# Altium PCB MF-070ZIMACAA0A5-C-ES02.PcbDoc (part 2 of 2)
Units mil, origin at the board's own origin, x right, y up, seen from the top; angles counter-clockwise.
Board outline 4023.75 x 4574.93 mil, 4 copper layers (TopLayer, LAYER2:GND, LAYER3:PW, BottomLayer); 140 components, 66 nets, 413 pads, 523 vias.
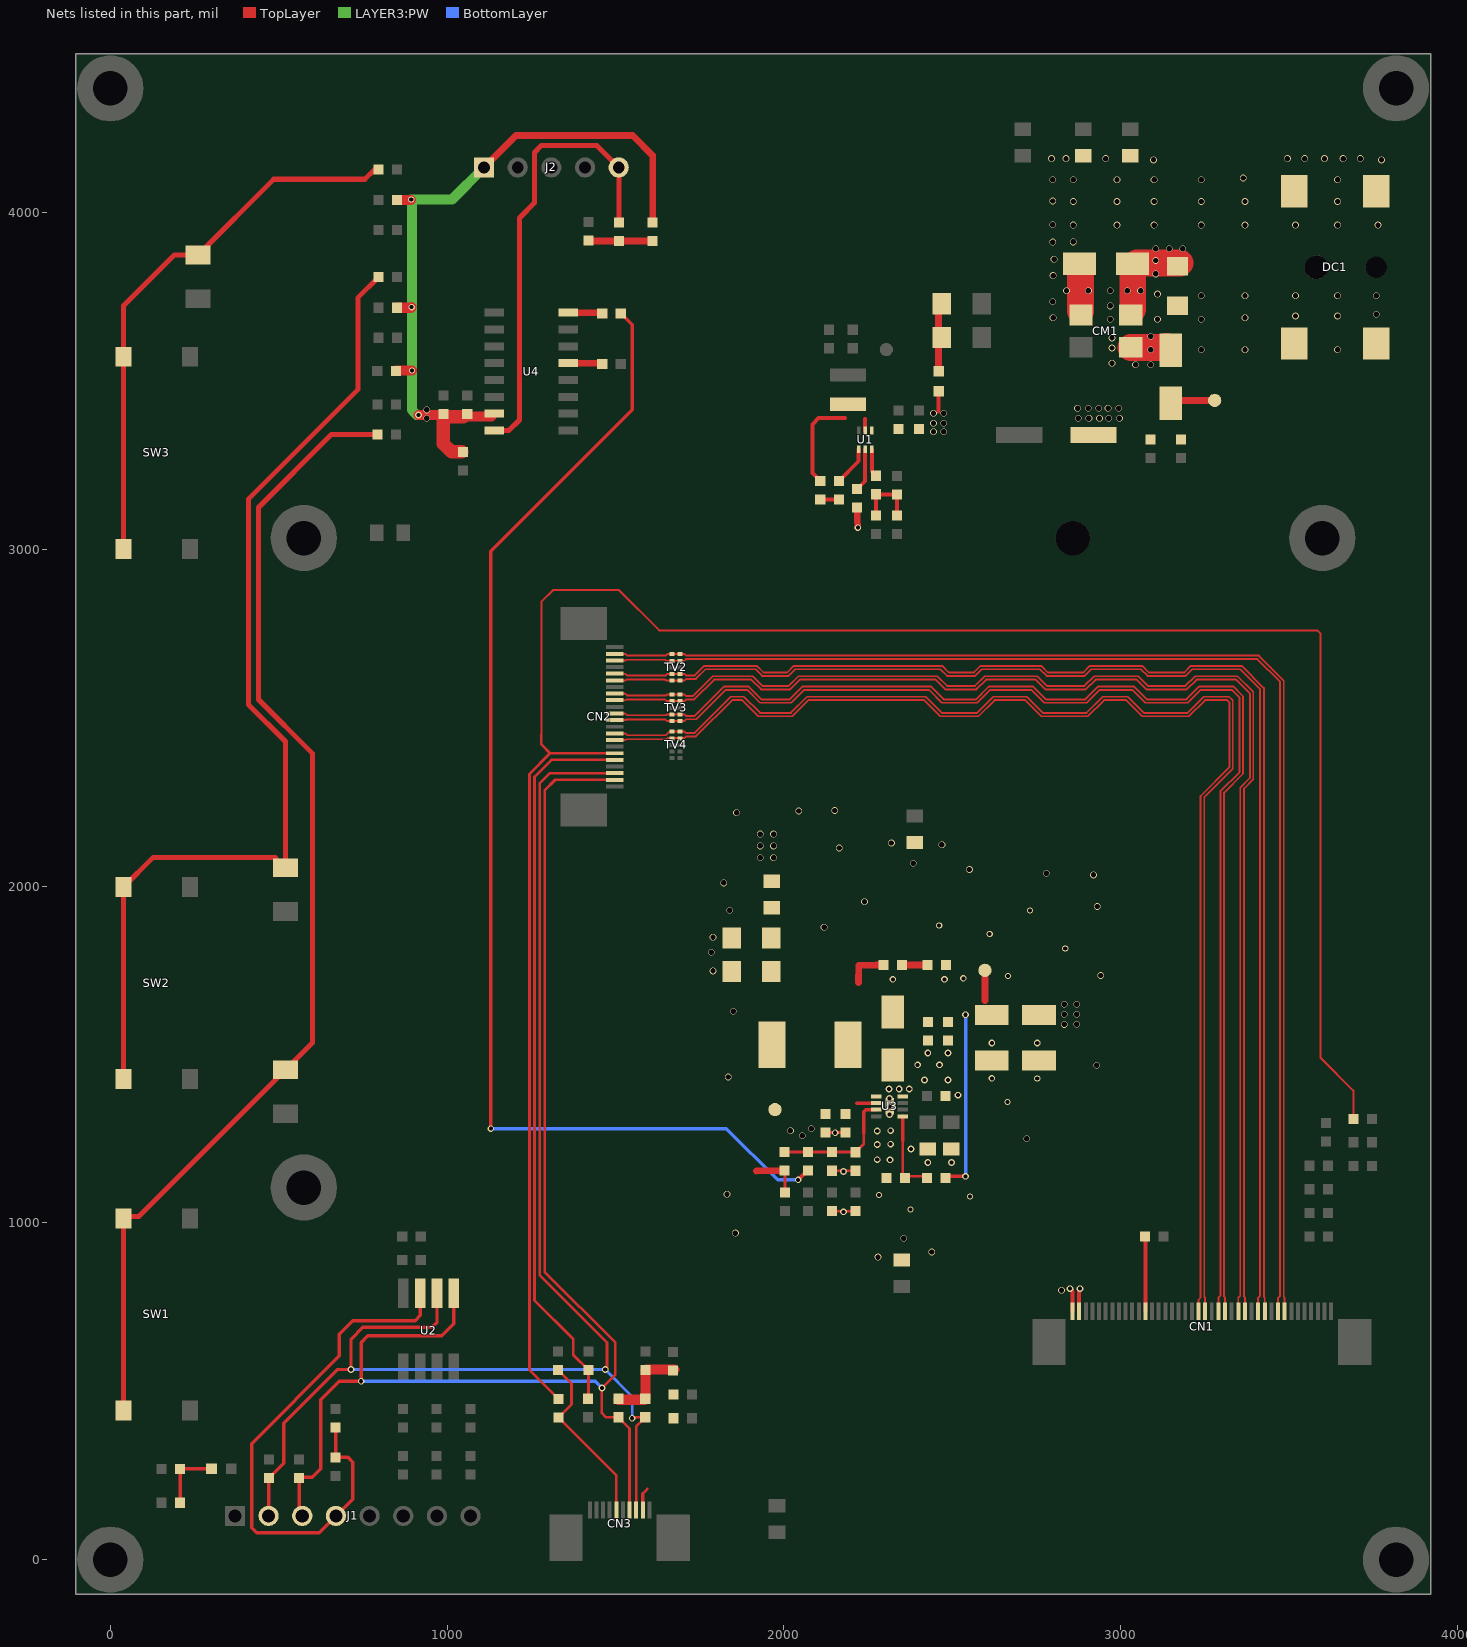
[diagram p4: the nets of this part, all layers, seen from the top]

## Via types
v1: diameter 20, hole 16, TopLayer to BottomLayer, 413 vias
v2: diameter 20, hole 12, TopLayer to BottomLayer, 77 vias
v3: diameter 18, hole 12, TopLayer to BottomLayer, 33 vias

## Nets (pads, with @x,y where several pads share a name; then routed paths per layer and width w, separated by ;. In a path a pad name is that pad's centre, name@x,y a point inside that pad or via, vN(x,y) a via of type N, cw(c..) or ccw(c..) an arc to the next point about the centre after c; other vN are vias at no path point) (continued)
LEDGND: B1.2 B2.2 C17.1 C18.1 C19.1 C20.1 C21.2 C22.1 C23.1 C24.2 C25.2 C35.1 CP5.2 CP6.2 R22.2 R25.2 R27.1 R29.1 R30.1 U3.4 U3.9 | length 202
  TopLayer w8: CP6.2@2123.87,1268.49 2152.48,1268.49 v2(2152.9,1268.07) 2153.32,1268.49 CP5.2@2183.87,1268.49 ; R25.2@2143.71,1035.29 2175.68,1035.29 v2(2177.9,1033.07) 2179.95,1035.12 C25.2@2212.78,1035.12 ; R22.2@2143.71,1155.29 2175.68,1155.29 v2(2177.9,1153.07) 2179.95,1155.12 C24.2@2212.78,1155.12
  other v1: 2280,898.74 2440,913.74 2356.67,955 1856.67,970 1831.67,1085 2721.67,1250 2055,1258.74 2020,1273.74 2081.67,1280.09 1835,1433.74 2930,1468.74 1850,1628.74 2941.67,1735 1790,1748.74 1785,1803.74 1790,1848.74 2120,1878.74 1840,1928.74 2931.67,1940 2240,1953.74 1821.67,2010 2920,2033.74 2780,2038.74 2551.67,2050 2385,2068.74 2165,2113.74 2470,2123.74 2320,2128.74 1860,2218.74 2045,2223.74 2151.67,2225
  other v2: 2428.07,1179.76 2498.07,1179.76 2277.9,1188.07 2316,1187.62 2378.07,1219.76 2277.9,1233.07 2317.64,1234.09 2277.9,1273.07 2317.64,1274.09 2314,1322.09 2314,1346.09 2314,1370.09 2517.38,1379.62 2312.9,1398.07 2342.9,1398.07 2372.9,1398.07 2418.07,1424.76 2488.07,1424.76 2618.07,1429.76 2398.07,1469.76 2463.07,1469.76 2428.07,1504.76 2488.07,1504.76 2618.07,1534.76 2753.07,1534.76 2324,1723.62 2477.38,1723.62 2533.38,1726.57
  other v3: 2376.22,1039.76 2553.07,1078.65 2283.07,1082.65 2664.22,1359.76 2753.07,1429.76 2665.92,1733.07 2836.22,1814.76 2611.92,1858.07 2461.92,1883.07 2731.92,1928.07
LX: D2.1 L3.1 R56.1 U3.5 | length 124.2
  TopLayer w20: 2222,1714.09 2223.07,1764.76 2274.37,1766.45 R56.1@2296.61,1766.45
MCU_3.3V: C27.1 C28.1 FB2.2 J2.1 R33.1 R37.1 R38.1 R39.1 U4.7 | length 2203.4
  TopLayer w20: J2.1@1110,4135 1204.65,4229.65 1551.53,4229.65 1610.72,4170.46 R33.1@1610.72,3971.88 ; U4.7@1131.84,3395.18 U4.7@1140.26,3403.6
  TopLayer w30: R37.1@847.93,3530.76 848.74,3531.57 v3(895.71,3531.57) ; R38.1@851.04,3718.48 893.48,3718.48 v2(895,3720) ; R39.1@851.04,4038.48 v3@893.01,4038.48 ; v2(915,3400) 987.16,3400 C28.1@990.12,3402.95 ; C27.1@1048.01,3394.25 1047.08,3395.18 U4.7@1131.84,3395.18
  TopLayer w40: FB2.2@1043.82,3290 1013.82,3290 988.94,3314.88 988.94,3395.18 C27.1@1048.94,3395.18
  LAYER3:PW w30: v2(915,3400) 910,3400 895.71,3414.29 895.71,4037.4 v3(893.82,4039.29) 1014.29,4039.29 J2.1@1110,4135 ; J2.1@1100.82,4139.65 J2.1@1119.91,4139.65
  other v1: 940,3390 940,3415
MIPI_0N: CN1.8 CN2.21 TV2.1 TV2.10 | length 3897.9
  TopLayer w5.5: CN2.21@1498.03,2690.44 1529.56,2690.44 1535,2685 1650,2685 1654.7,2689.7 1705.3,2689.7 1710,2685 3411.26,2685 3485.29,2610.97 3485.29,780.93 ; 3485.29,780.93 3487.91,778.31 CN1.8@3487.91,738.19
MIPI_0P: CN1.9 CN2.20 TV2.2 TV2.9 | length 3880.3
  TopLayer w5.5: CN2.20@1498.03,2670.75 1530.75,2670.75 1532.93,2672.93 1647.93,2672.93 1650.84,2670.02 TV2.9@1692.14,2670.02 ; TV2.9@1692.14,2670.02 1705.02,2670.02 1710,2675 3407.12,2675 3474.22,2607.9 3474.22,784 3468.23,778.01 CN1.9@3468.23,738.19
MIPI_1N: CN1.11 CN2.18 TV2.4 TV2.7 | length 3889.7
  TopLayer w5.5: CN2.18@1498.03,2631.38 1529.56,2631.38 1535,2625.94 1650,2625.94 1654.7,2630.65 1692.14,2630.65 1705.3,2630.65 1710,2625.94 1735,2625.94 1763.56,2654.5 1920.5,2654.5 1940,2635 2010.5,2635 2030,2654.5 2470.5,2654.5 2490,2635 2565,2635 2584.5,2654.5 2765.27,2654.5 2784.77,2635 2890,2635 2909.5,2654.5 3065.27,2654.5 3084.77,2635 3190,2635 3209.5,2654.5 3360.5,2654.5 3426.24,2588.76 3426.24,780.93 3428.86,778.31 CN1.11@3428.86,738.19
MIPI_1P: CN1.12 CN2.17 TV2.5 TV2.6 | length 3872.1
  TopLayer w5.5: CN2.17@1498.03,2611.7 1530.75,2611.7 1532.93,2613.87 1647.93,2613.87 1650.84,2610.96 1692.14,2610.96 1705.02,2610.96 1710,2615.94 1739.14,2615.94 1767.7,2644.5 1916.36,2644.5 1935.86,2625 2014.64,2625 2034.14,2644.5 2465.5,2644.5 2485,2625 2569.14,2625 2588.64,2644.5 2761.12,2644.5 2780.62,2625 2894.14,2625 2913.64,2644.5 3061.12,2644.5 3080.62,2625 3194.14,2625 3213.64,2644.5 3356.36,2644.5 3415.17,2585.69 3415.17,784 3409.17,778.01 CN1.12@3409.17,738.19
MIPI_2N: CN1.17 CN2.12 TV3.4 TV3.7 | length 3898
  TopLayer w5.5: CN2.12@1498.03,2513.27 1529.56,2513.27 1535,2507.83 1650,2507.83 1652.81,2510.65 1692.14,2510.65 1705.3,2510.65 1710,2505.94 1735.94,2505.94 1823.5,2593.5 1895.23,2593.5 1933.73,2555 2018.13,2555 2056.63,2593.5 2436.5,2593.5 2475,2555 2571.27,2555 2609.77,2593.5 2740,2593.5 2778.5,2555 2896.27,2555 2934.77,2593.5 3040,2593.5 3078.5,2555 3196.27,2555 3234.77,2593.5 3335.23,2593.5 3364.17,2564.57 3364.17,2334.17 3308.13,2278.13 3308.13,780.93 3310.75,778.31 CN1.17@3310.75,738.19
MIPI_2P: CN1.18 CN2.11 TV3.5 TV3.6 | length 3882.9
  TopLayer w5.5: CN2.11@1498.03,2493.59 1530.75,2493.59 1532.93,2495.76 1647.93,2495.76 1652.73,2490.96 1692.14,2490.96 1705.02,2490.96 1710,2495.94 1740.09,2495.94 1827.64,2583.5 1891.09,2583.5 1929.59,2545 2022.27,2545 2060.77,2583.5 2431.5,2583.5 2470,2545 2575.41,2545 2613.91,2583.5 2735.86,2583.5 2774.36,2545 2900.41,2545 2938.91,2583.5 3035.86,2583.5 3074.36,2545 3200.41,2545 3238.91,2583.5 3331.09,2583.5 3354.17,2560.43 3354.17,2339.17 3297.06,2282.06 3297.06,784 3291.06,778.01 CN1.18@3291.06,738.19
MIPI_3N: CN1.20 CN2.9 TV4.1 TV4.10 | length 3902.6
  TopLayer w5.5: CN2.9@1498.03,2454.22 1529.56,2454.22 1535,2448.78 1649.08,2448.78 1660,2459.7 1692.14,2459.7 1705.3,2459.7 1710,2455 1735,2455 1843,2563 1882,2563 1930,2515 2021.26,2515 2069.26,2563 2422,2563 2470,2515 2574.4,2515 2622.4,2563 2722,2563 2770,2515 2899.4,2515 2947.4,2563 3022,2563 3070,2515 3199.4,2515 3247.4,2563 3322.6,2563 3333.67,2551.93 3333.67,2348.67 3249.07,2264.07 3249.07,780.93 3251.69,778.31 CN1.20@3251.69,738.19
MIPI_3P: CN1.21 CN2.8 TV4.2 TV4.9 | length 3882.6
  TopLayer w5.5: CN2.8@1498.03,2434.53 1530.75,2434.53 1532.93,2436.71 1651.69,2436.71 1655,2440.02 1692.14,2440.02 1705.02,2440.02 1710,2445 1739.14,2445 1847.14,2553 1877,2553 1925,2505 2025.4,2505 2073.4,2553 2417,2553 2465,2505 2578.54,2505 2626.54,2553 2717,2553 2765,2505 2903.54,2505 2951.54,2553 3017,2553 3065,2505 3203.54,2505 3251.54,2553 3317,2553 3323.67,2546.33 3323.67,2353.67 3238,2268 3238,778 3232.01,772.01 CN1.21@3232.01,738.19
MIPI_CLKN: CN1.14 CN2.15 TV3.1 TV3.10 | length 3893.4
  TopLayer w5.5: CN2.15@1498.03,2572.33 1529.56,2572.33 1535,2566.89 1650,2566.89 1652.81,2569.7 1692.14,2569.7 1705.3,2569.7 1710,2565 1730,2565 1789,2624 1907.87,2624 1936.87,2595 2015,2595 2044,2624 2456,2624 2485,2595 2568.13,2595 2597.13,2624 2752.63,2624 2781.63,2595 2893.13,2595 2922.13,2624 3052.63,2624 3081.63,2595 3193.13,2595 3222.13,2624 3347.87,2624 3394.67,2577.2 3394.67,2317.48 3367.18,2290 3367.18,780.93 3369.8,778.31 CN1.14@3369.8,738.19
MIPI_CLKP: CN1.15 CN2.14 TV3.2 TV3.9 | length 3878.3
  TopLayer w5.5: CN2.14@1498.03,2552.64 1530.75,2552.64 1532.93,2554.82 1647.93,2554.82 1652.73,2550.02 1692.14,2550.02 1705.02,2550.02 1710,2555 1734.14,2555 1793.14,2614 1903.72,2614 1932.72,2585 2019.14,2585 2048.14,2614 2451,2614 2480,2585 2572.28,2585 2601.28,2614 2748.49,2614 2777.49,2585 2897.28,2585 2926.28,2614 3048.49,2614 3077.49,2585 3197.28,2585 3226.28,2614 3343.72,2614 3384.67,2573.06 3384.67,2321.63 3356.11,2293.07 3356.11,784 3350.12,778.01 CN1.15@3350.12,738.19
N14289089: DC1.5 F1.2
  other v1: 3240.08,3593.86 3370.08,3593.86 3645.08,3593.86 3110.08,3683.86 3240.08,3683.86 3370.08,3688.86 3520.08,3693.86 3645.08,3693.86 3760.08,3698.86 3240.08,3753.86 3370.08,3753.86 3520.08,3753.86 3645.08,3753.86 3760.08,3753.86 3110.08,3758.86
N14289101: CM1.1 F1.1 TV1.2 | length 270.5
  TopLayer w80: CM1.1@3036.77,3713.69 3036.77,3838.69 3041.77,3843.69 3048.72,3850.63 F1.1@3177.32,3850.63
  other v1: 2970.08,3683.86 2970.08,3723.86 2970.08,3768.86 3020.08,3768.86 3060.08,3768.86 3105.08,3818.86 3105.08,3858.86 3105.08,3893.86 3145.08,3893.86 3185.08,3893.86
N14289105: CM1.2 D1.1 | length 107.2
  TopLayer w80: CM1.2@3030.77,3600.76 3133.84,3600.76 D1.1@3136.77,3603.69
  other v1: 3045.08,3548.86 3090.08,3548.86 2975.08,3553.86 3090.08,3593.86 2975.08,3598.86 2975.08,3628.86 3090.08,3633.86
N14289125: B5.2 B6.2 CM1.4 DC1.3 DC1.4 TV1.1 | length 126.7
  TopLayer w80: CM1.4@2881.77,3708.69 TV1.1@2881.77,3835.36
  other v1: 2800.08,3688.86 2799.21,3736.22 2840.08,3768.86 2905.08,3768.86 2800.08,3813.86 2803.15,3862.2 2799.21,3913.39 2860.08,3913.86 2860.08,3963.86 2990.08,3963.86 3100.08,3963.86 3240.08,3963.86 3370.08,3963.86 3520.08,3963.86 3645.08,3963.86 3765.08,3963.86 2799.21,3964.57 2860.08,4033.86 2990.08,4033.86 3100.08,4033.86 3240.08,4033.86 3370.08,4033.86 3645.08,4033.86 2799.21,4035.43 2799.21,4098.43 2860.08,4098.86 2990.08,4098.86 3100.08,4098.86 3240.08,4098.86 3645.08,4098.86 3365.08,4103.86 3098.43,4157.48 3775.59,4157.48 2795.28,4161.42 2838.58,4161.42 2956.69,4161.42 3496.06,4161.42 3547.24,4161.42 3606.3,4161.42 3661.42,4161.42 3712.6,4161.42
N14506503: C21.1 R56.2 | length 74.5
  TopLayer w20: R56.2@2352.11,1765.95 C21.1@2426.61,1765.95
N14509647: R2.1 U1.4 | length 118.7
  TopLayer w11.81: R2.1@2163.77,3203.77 2222.49,3262.49 U1.4@2222.49,3298.11
N14509651: C4.2 R2.2 | length 54.6
  TopLayer w11.81: C4.2@2109.15,3148.77 R2.2@2163.77,3148.77
N14509727: C4.1 L1.1 U1.2 | length 317.8
  TopLayer w11.81: C4.1@2108.65,3203.27 2085.03,3226.89 2085.03,3372.01 2103.65,3390.63 2182.39,3390.63 ; U1.2@2242.17,3353.23 2242.17,3387.42
N14509879: R1.2 U1.5 | length 128.3
  TopLayer w11.81: R1.2@2218.21,3179.74 2242.17,3203.7 U1.5@2242.17,3298.11
N14509925: R3.1 U1.6 | length 83.6
  TopLayer w11.81: U1.6@2261.86,3298.11 2261.86,3231.67 R3.1@2274,3219.52
N14510061: C5.1 R3.2 R4.1 R5.1 | length 189.1
  TopLayer w11.81: R5.1@2274,3101.41 R3.2@2274,3164.52 2274.41,3164.11 R4.1@2336.32,3164.11 2337,3163.44 C5.1@2337,3100.91
N14543357: C26.1 R33.2 R34.2 | length 190
  TopLayer w20: C26.1@1420.76,3916.88 R33.2@1610.72,3916.88
N14572856: R36.2 U4.13 | length 102
  TopLayer w20: U4.13@1359.95,3553.6 1458.85,3553.6 R36.2@1461.04,3551.41
N14573902: R57.2 SW1.A SW1.B TV7.1 | length 3449.9
  TopLayer w15: SW1.B@39.37,442.91 39.37,1019.37 84.51,1019.37 600,1534.86 600,2395 440,2555 440,3125 656.57,3341.57 R57.2@793.21,3341.57
N14573940: R58.2 SW2.A SW2.B TV8.1 | length 3060
  TopLayer w15: SW2.B@39.37,1427.17 SW2.A@39.37,1998.03 126.34,2085 490.14,2085 TV8.1@520.14,2055 520.14,2429.86 410,2540 410,3150 735,3475 735,3747.97 R58.2@796.32,3809.29
N14573978: R59.2 SW3.A SW3.B TV9.1 | length 1647.1
  TopLayer w15: SW3.B@39.37,3001.97 39.37,3724.37 190,3875 TV9.1@260.14,3875 485.14,4100 755.71,4100 785,4129.29 R59.2@796.32,4129.29
N14631898: R35.2 U4.16 | length 102
  TopLayer w20: U4.16@1359.95,3703.6 1458.85,3703.6 R35.2@1461.04,3701.41
N14687410: LED2.2 R66.1 R67.1 | length 208.2
  TopLayer w20: LED2.2@2460,3526.81 R67.1@2460,3735
N14705498: LED1.2 R71.1 R72.1 | length 193.6
  TopLayer w10: R71.1@207.24,169 R72.1@207.24,269 208.24,270 LED1.2@300.47,270
OVP: R27.2 R28.1 U3.1 | length 249
  TopLayer w8: 2353.37,1244.07 2353.37,1138.69 2353.62,1138.44 R28.1@2424.42,1138.44
  TopLayer w10: 2353.37,1244.07 U3.1@2353.37,1316.56
PCT_3.3V: C11.1 C12.1 C13.1 CN3.2 FB3.2 R17.2 R18.2 | length 319.4
  TopLayer w8: 1581.61,196.61 1595,210
  TopLayer w10: CN3.2@1581.61,147.64 1581.61,196.61
  TopLayer w30: R18.2@1510,475 1585.96,475 1589.97,479.01 C13.1@1589.97,563.02 1591.95,565 FB3.2@1675,565
PCT_INT1: C15.1 CN2.5 R19.2 | length 2171.2
  TopLayer w8: R19.2@1419.97,479.01 C15.1@1419.97,563.02 1375,608 1375,655 1260,770 1260,2325 1310.48,2375.48 CN2.5@1498.03,2375.48
PCT_RST1: CN2.6 R20.1 R73.2 | length 6496.2
  TopLayer w6: 1280,2450 1280,2845 1315,2880 1510,2880 1630,2760 3585,2760 3595,2750 3595,1490 3692.24,1392.76 R73.2@3692.24,1309
  TopLayer w8: 1280,2450 1280,2421.7 1306.53,2395.16 ; R20.1@1331.13,477.09 1245,563.22 1245,2333.63 1306.53,2395.16 ; CN2.6@1498.03,2395.16 1306.53,2395.16
PCT_RST2: C16.1 CN3.6 R20.2 | length 519.2
  TopLayer w8: C16.1@1329.97,563.02 1370,523 1370,460.96 R20.2@1331.13,422.09 1502.87,250.34 CN3.6@1502.87,147.64
PWM: R24.1 R35.1 | length 3626
  TopLayer w10: v2(1130,1280) 1130,2995 1550,3415 1550,3667.45 R35.1@1516.04,3701.41
  TopLayer w12: v2(2042.9,1128.07) 2070.68,1155.85 R24.1@2072.09,1155.85
  BottomLayer w10: v2(1130,1280) 1830,1280 1981.93,1128.07 v2(2042.9,1128.07)
PWM1: C24.1 R21.2 R22.1 R24.2 U3.7 | length 380
  TopLayer w8: R21.2@2002.09,1210.85 2213.51,1210.85 2238,1235.34 2238,1266.09
  TopLayer w10: 2238,1266.09 2238,1330.09 2244.16,1336.25 U3.7@2274.63,1336.25
RESET_H: J2.5 R34.1 U4.8 | length 1349.9
  TopLayer w15: U4.8@1140.26,3353.6 1183.6,3353.6 1215,3385 1215,3985 1259.91,4029.91 1259.91,4179.65 1280.26,4200 1445,4200 1510.72,4134.28 R34.1@1510.72,3971.88
RX_SCL: CN2.3 CN3.3 J1.2 R7.2 R17.1 U2.6 | length 4332.4
  TopLayer w8: v2(1470,565) 1475,570 1475,645 1275,845 1275,2305 1306.11,2336.11 CN2.3@1498.03,2336.11 ; v2(1550,420) 1552.91,422.91 R17.1@1588.87,422.91 1561.93,395.97 CN3.3@1561.93,147.64
  TopLayer w10: J1.2@470,130 470.81,130.81 R7.2@470.81,242.22 515,286.41 515,405 675,565 v2(715,565) 715,655 750,690 955,690 970.31,705.31 U2.6@970.31,791.2
  BottomLayer w8: v2(1470,565) 1550,485 v2(1550,420)
  BottomLayer w10: v2(715,565) v2(1470,565)
RX_SDA: CN2.2 CN3.4 J1.3 R8.2 R18.1 U2.5 | length 4284.5
  TopLayer w8: CN2.2@1498.03,2316.42 1321.42,2316.42 1290,2285 1290,855 1500,645 1500,550 v2(1460,510) 1460,435 1472.09,422.91 R18.1@1508.87,422.91 1542.24,389.54 CN3.4@1542.24,147.64
  TopLayer w10: J1.3@570,130 560.81,139.19 R8.2@560.81,242.22 563.59,245 600,245 625,270 625,475 680,530 v2(745,530) 745,645 765,665 985,665 1020.31,700.31 U2.5@1020.31,791.2
  BottomLayer w10: v2(745,530) 1440,530 v2(1460,510)
VCL: C36.1 CN1.29 | length 222.5
  TopLayer w12: C36.1@3072.94,960.07 3074.53,958.48 CN1.29@3074.53,738.19
VIN: C1.1 C2.1 C3.1 CP1.1 CP2.1 D1.2 LED2.1 R1.1 R32.1 TP1.1 U1.1 | length 244.5
  TopLayer w12: 2460,3410 LED2.1@2460,3470.47
  TopLayer w20: R1.1@2218.21,3124.74 2218.21,3093.23 v2(2220,3065) ; D1.2@3155.8,3443.14 TP1.1@3279.98,3443.14
  other v1: 1930,2085 1970,2085 1930,2120 1970,2120 1930,2155 1970,2155 2445,3350 2475,3350 2445,3375 2475,3375 2875,3390 2906.5,3390 2937.99,3390 2965.55,3390 2997.05,3390 2445,3405 2475,3405 2872.95,3420 2904.45,3420 2935.94,3420 2963.5,3420 2995,3420
VLED: C22.2 C23.2 CP5.1 CP6.1 L3.2 R21.1 R23.1 R32.2 TP3.1 U3.6 | length 204.9
  TopLayer w8: R23.1@2003.71,1090.29 R21.1@2003.71,1154.23
  TopLayer w10: 2216.32,1355.93 U3.6@2274.63,1355.93
  TopLayer w20: 1919.41,1154.57 R21.1@2002.09,1155.85
VOUT: C18.2 C19.2 C20.2 C35.2 CN1.39 CN1.40 D2.2 R28.2 TP6.1 | length 769
  TopLayer w10: R28.2@2479.42,1138.44 v2(2540.21,1138.44)
  TopLayer w12: v2(2850,805) 2857.99,797.01 CN1.40@2857.99,738.19 ; CN1.39@2877.68,738.19 2877.68,802.68 v2(2880,805)
  TopLayer w20: 2597.82,1660.02 TP6.1@2597.82,1750.29
  BottomLayer w10: v2(2540.21,1138.44) v2(2540.21,1618.44)
  other v1: 2825,800 2833.07,1589.76 2870,1590 2833.07,1619.76 2870,1620 2833.07,1649.76 2870,1650
WP: J1.4 R15.1 R16.2 U2.7 | length 1614.8
  TopLayer w10: R15.1@669.19,392.78 R16.2@669.19,304.04 705.96,304.04 720,290 720,180 620,80 435,80 420,95 420,345 680,605 680,670 720,710 905,710 920.31,725.31 U2.7@920.31,791.2
pads on no net: CN1.1 CN1.6 CN1.23 CN1.24 CN1.26 CN1.27 CN1.28 CN1.33 CN1.34 CN1.35 CN1.36 CN1.37 CN1.38 CN1.G CN2.G CN3.7 CN3.8 CN3.9 CN3.G DC1.NC TV4.4 TV4.5 TV4.6 TV4.7 U4.6 U4.9 U4.10 U4.11 U4.12 U4.14

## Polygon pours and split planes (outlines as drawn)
FGND on TopLayer "TopLayer-FGND" (hatched 90Degree grid 5 track 6, remove dead copper, pour order 0): 3960,4520 3815,4520 3815,3160 3485,3160 3485,2920 3815,2920 3815,-270 4085,-270 4085,4545
FGND on TopLayer "TopLayer-FGND 1" (hatched 90Degree grid 5 track 6, remove dead copper, pour order 1): 4145,4540 -190,4540 -190,-190 4125,-190 4125,105 2675,105 2675,20 140,20 0,160 0,355 250,355 440,545 440,995 670,995 700,1015 700,1260 700,2245 700,2755 700,2795 700,2835 700,2885 700,3150 695,3790 695,4225 695,4260 695,4290 695,4355 4150,4355
LEDGND on TopLayer "TopLayer-LEDGND" (hatched 90Degree grid 5 track 6, remove dead copper, pour order 2): 2970,2150 2970,1385 2445,860 1885,860 1775,970 1775,2230 1805,2260 2155,2260 2260,2155
N14509727 on TopLayer "TopLayer-N14509727" (hatched 90Degree grid 4 track 4, remove dead copper, pour order 3): 2242.17,3387.42 2270,3415.25 2285,3430.25 2285,3460 2275,3470 2065,3470 2055,3460 2055,3195 2065,3185 2120,3185 2120,3225 2100,3245 2100,3365 2115,3380 2230,3380
GND on TopLayer "TopLayer-GND" (hatched 90Degree grid 1 track 2, remove dead copper, pour order 4): 3570,2745 1480,2745 1480,2410 3190,2410 3190,715 3570,715
GND on TopLayer "TopLayer-GND 1" (hatched 90Degree grid 6 track 6, remove dead copper, pour order 5): 4340,4680 -345,4680 -345,-470 4115,-470
GND on LAYER2:GND "LAYER2:GND-GND" (hatched 90Degree grid 5 track 6, remove dead copper, pour order 6): 4285,4615 -240,4615 -240,-625 4220,-625
FGND on LAYER2:GND "LAYER2:GND-FGND" (hatched 90Degree grid 5 track 6, remove dead copper, pour order 7): 3820,4635 3820,3170 3475,3170 3475,2920 3810,2920 3810,-315 4195,-315 4195,4645
FGND on LAYER2:GND "LAYER2:GND-FGND 1" (hatched 90Degree grid 5 track 6, remove dead copper, pour order 8): 4195,4575 -215,4575 -215,-290 4030,-290 4030,105 2680,105 2680,25 140,25 5,160 5,355 245,355 440,550 440,995 670,995 700,1010 700,1255 700,4350 2685,4350 2685,4215 4180,4215
LEDGND on LAYER2:GND "LAYER2:GND-LEDGND" (hatched 90Degree grid 5 track 6, remove dead copper, pour order 9): 2970,2155 2260,2155 2155,2260 1800,2260 1775,2235 1775,970 1880,865 2440,865 2960,1385
GND on LAYER3:PW "LAYER3:PW-GND" (hatched 90Degree grid 6 track 6, remove dead copper, pour order 10): 4545,4615 -330,4615 -330,-300 4585,-300
FGND on LAYER3:PW "LAYER3:PW-FGND" (hatched 90Degree grid 5 track 6, remove dead copper, pour order 11): 3800,4630 3800,3170 3480,3170 3480,2925 3800,2925 3800,-410 4130,-410 4130,4725
FGND on LAYER3:PW "LAYER3:PW-FGND 1" (hatched 90Degree grid 5 track 6, remove dead copper, pour order 12): 4150,4585 -385,4585 -385,-235 3940,-235 3940,110 2655,110 2655,25 145,25 20,150 20,345 240,345 440,545 440,1000 655,1000 705,1035 705,1260 705,4345 2695,4345 2695,4205 4145,4205
LEDGND on LAYER3:PW "LAYER3:PW-LEDGND" (hatched 90Degree grid 5 track 6, remove dead copper, pour order 13): 2970,2155 2255,2155 2155,2255 1795,2255 1770,2230 1770,975 1890,855 2455,855 2975,1375
GND on BottomLayer "BottomLayer-GND" (hatched 90Degree grid 6 track 6, remove dead copper, pour order 14): 4220,4590 -255,4590 -255,-495 4210,-495
FGND on BottomLayer "BottomLayer-FGND" (hatched 90Degree grid 5 track 6, remove dead copper, pour order 15): 3800,4540 3800,3165 3475,3165 3475,2910 3805,2910 3805,-365 4210,-365 4210,4545
FGND on BottomLayer "BottomLayer-FGND 1" (hatched 90Degree grid 5 track 6, remove dead copper, pour order 16): 4135,4595 -255,4595 -255,-255 4030,-255 4030,105 2665,105 2665,20 145,20 10,155 10,345 230,345 450,565 450,985 705,985 705,4350 2685,4350 2685,4205 4125,4205
LEDGND on BottomLayer "BottomLayer-LEDGND" (hatched 90Degree grid 5 track 6, remove dead copper, pour order 17): 2970,2160 2245,2160 2145,2260 1810,2260 1775,2225 1775,980 1885,870 2455,870 2960,1375

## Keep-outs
KeepOutLayer:
  lines w5: -98.43,-78.74 ccw(c-78.74,-78.74) -78.74,-98.43 1355.12,-98.43 cw(c1374.8,-98.43) 1374.8,-78.74 1650.39,-78.74 cw(c1650.39,-98.43) 1670.08,-98.43 3897.64,-98.43 ccw(c3897.64,-78.74) 3917.32,-78.74 3917.32,4448.82 ccw(c3897.64,4448.82) 3897.64,4468.5 -78.74,4468.5 ccw(c-78.74,4448.82) -98.43,4448.82 -98.43,-78.74

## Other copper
TopLayer:
  rectangle net N14509727: 2100,3392.74 2245,3468.4
  rectangle net FGND: 690,3008.74 830,3095
  rectangle net FGND: 1925,8.74 2030,120
  rectangle net PCT_3.3V: 1580,270 1700,340
  rectangle net PCT_3.3V: 1635,270 1700,585
  rectangle net PCT_3.3V: 1580,190 1620,285
  rectangle net EEPROM_3.3V: 830,785 890,1045
  rectangle net EEPROM_3.3V: 1530,985 1595,2305
  rectangle net 3.3V: 1640,605 1720,705
  region net LEDGND: 2203.07,1289.76 1978.07,1289.76 1978.07,1244.76 2203.07,1244.76
  region net VLED: 1968.07,1314.76 1907.6,1314.76 1907.6,1140 1968.07,1140
  rectangle net VIN: 2850,3310 3220.47,3507.87
  rectangle net N14289105: 2965.08,3528.86 3195.08,3648.86
  rectangle net N14289089: 3210.08,3563.86 3805.08,3773.86
  rectangle net N14289089: 3100.08,3670 3800,3773.86
  rectangle net N14289101: 2945.93,3668.86 3075.08,3908.86
  rectangle net N14289101: 2960.08,3788.86 3228.35,3920.86
  rectangle net N14289125: 2763.78,3648.86 2925.08,4113.86
  rectangle net N14289125: 2767.72,3933.86 3800.08,4188.98
  rectangle net 3.3V: 2020,3490 2256.23,3615.21
  rectangle net GND: 2196.23,3317.02 2292.56,3333.02
  rectangle net N14509727: 2124.08,3400.21 2261.23,3477.02
  rectangle net VIN: 2261.23,3340.21 2525,3385
  rectangle net VLED: 1908.07,1348.09 2063.07,1965
  rectangle net VLED: 1907.6,1298.09 2216.32,1355.93
  rectangle net LEDGND: 2301,1102.79 2325,1380
  rectangle net LEDGND: 2302.01,1370.09 2391.92,1403.62
  rectangle net LX: 2094,1370.09 2243.07,1774.76
  rectangle net LX: 2094.01,1419.62 2358.01,1554.09
  rectangle net 3.3V: 1020,3177.93 1110,3257.22
  region net LX: 2288.07,1404.76 2233.07,1404.76 2233.07,1369.76 2288.07,1369.76
  rectangle net MCU_3.3V: 910,3380 1180,3430
  rectangle net FGND: 2685.04,4208.66 3897.64,4448.82
  rectangle net LCM_3.3V: 3590,785 3645,1255
  rectangle net EEPROM_3.3V: 3580,1275 3665,1385
  rectangle net VIN: 2435,3340 2525,3420
  region net VOUT: 2890,1669.76 2268.07,1669.76 2268.07,1574.76 2890,1574.76
  rectangle net VOUT: 2815,785 2890,830
  rectangle net VIN: 1915,1985 2060,2170
  rectangle net 3.3V: 1930,3025 2035,3615
  text ".Layer_Name" at 1300,4600 h120
LAYER2:GND:
  text ".Layer_Name" at 1400,4600 h120
LAYER3:PW:
  rectangle net EEPROM_3.3V: 830,985 1595,1045
  rectangle net 3.3V: 1625,650 1725,1165
  rectangle net 3.3V: 880,1070 1725,1165
  rectangle net MCU_3.3V: 905,3380 960,3430
  rectangle net VIN: 2445,3295 3030,3445
  rectangle net VIN: 2861.93,3378.7 3023.35,3435
  rectangle net VIN: 1225,2920 2470,3080
  rectangle net VIN: 2430,2920 2595,3445
  rectangle net N14289089: 3100.08,3668.86 3805.08,3773.86
  rectangle net N14289089: 3210.08,3563.86 3810.08,3773.86
  rectangle net N14289125: 2763.78,3933.86 3800.08,4188.98
  rectangle net N14289125: 2763.78,3648.86 2925.08,4113.86
  rectangle net N14289101: 2960.08,3788.86 3228.35,3917.32
  rectangle net N14289101: 2941.93,3668.86 3080.08,3908.86
  rectangle net N14289105: 2965.08,3528.86 3195.08,3648.86
  rectangle net VOUT: 2815,790 2890,1670
  rectangle net VIN: 1150,2120 1285,3080
  rectangle net VIN: 1150,2060 2005,2175
  rectangle net 3.3V: 1220,3195 2035,3274.29
  rectangle net 3.3V: 880,3195 1335,3275
  rectangle net 3.3V: 880,1080 980,3275
  rectangle net EEPROM_3.3V: 3570,460 3670,1400
  rectangle net EEPROM_3.3V: 1540,450 3670,540
  rectangle net EEPROM_3.3V: 1510,450 1595,1045
  text ".Layer_Name" at 1345,4625 h120
BottomLayer:
  text ".Layer_Name" at 2445,4650 h120

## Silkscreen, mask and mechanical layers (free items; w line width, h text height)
TopOverlay:
  circle w10: c3293.35,4171.39 r7.23
  circle w5: c3293.35,4171.39 r9.46
  circle w5: c3427.76,4171.39 r31.52
  circle w5: c3158.93,4171.39 r31.52
  lines w5: 3190.45,4171.39 3261.83,4171.39 ; 3293.35,4171.39 3396.24,4171.39 ; 3309.11,4144.09 cw(c3293.35,4171.39) 3309.11,4198.69
  lines w6: 2663.82,2194.74 2663.82,2057.18 3423.56,2057.18 3423.56,2195 2665,2195 ; 2953.82,2229.74 2953.82,2359.74 ; 2955,2060 2955,2195 ; 2663.82,2228.02 3423.82,2228.02 3423.82,2359.74 2663.82,2359.74 2663.82,2228.02
  text ".Layer_Name" at 1300,4615 h120
  text "-" at 3141.58,4147.17 h50
  text "+" at 3411.58,4147.17 h50
  text "12V" at 3110.08,4068.86 h50
  text "3.3V" at 2260,3635 h40
  text "ON/OFF" at 421.26,3448.82 h60 r270
  text "VIN" at 3325.08,3418.86 h40
  text "7.0\" 800x1280 DSI Display with Capacitive Touch" at 1920,2813.74 h50
  text "PROC172A" at 2666.67,2387.57 h50
  text "OPN#" at 2690.44,2264.25 h60
  text "SK-LCD3" at 3040,2265 h50
  text "SL#" at 2735,2100 h60
  text "For Evaluation only, not FCC approved for resale" at 2155,1958.74 h50
  text "VOUT" at 2540,1800 h40
  text "UP" at 437.01,1787.4 h50 r270
  text "VLED" at 1835,1320 h30
  text "DOWN" at 464.57,826.77 h50 r270
  text "UL E321380" at 2326.67,360 h40
BottomOverlay:
  text ".Layer_Name" at 2275,4635 h100
  text "311-0701000005-ES02" at 3598.43,220.47 h60
TopSolder:
  text ".Layer_Name" at 1320,4615 h120
BottomSolder:
  text ".Layer_Name" at 2420,4630 h120
Mechanical1:
  lines w5: -98.43,-78.74 ccw(c-78.74,-78.74) -78.74,-98.43 1355.12,-98.43 cw(c1374.8,-98.43) 1374.8,-78.74 1650.39,-78.74 cw(c1650.39,-98.43) 1670.08,-98.43 3897.64,-98.43 ccw(c3897.64,-78.74) 3917.32,-78.74 3917.32,4448.82 ccw(c3897.64,4448.82) 3897.64,4468.5 -78.74,4468.5 ccw(c-78.74,4448.82) -98.43,4448.82 -98.43,-78.74
Mechanical2:
  drawing of 1355 lines, arcs and shapes, not listed
  text "DC1" at 3338.39,3786.31 h47.24 r90
  text "SW" at 419.31,3514.14 h39.37 r270
  text "1 BL ON/OFF" at 420.13,3445.51 h39.37 r270
  text "1" at 2405.7,3239.91 h86.51 r270
  text "CN2" at 1566.8,2720.9 h47.24 r270
  text "2" at 3075.06,2567.34 h86.51 r270
  text "SW" at 419.31,1939.34 h39.37 r270
  text "2 BL UP" at 420.13,1868.32 h39.37 r270
  text "SW" at 419.31,955.08 h39.37 r270
  text "3 BL DOWN" at 420.13,884.06 h39.37 r270
  text "CN1" at 2851.75,788.44 h47.24
  text "CN3" at 1410.17,218.04 h47.24
  text "1" at 1612.35,172.56 h47.24
DrillDrawing:
  text ".Layer_Name" at 1465,4605 h120
  text ".Legend" at -50,4525 h60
